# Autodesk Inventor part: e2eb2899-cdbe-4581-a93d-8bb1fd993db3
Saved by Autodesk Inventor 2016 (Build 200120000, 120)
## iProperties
Created: 2017-09
Part Number: e2eb2899-cdbe-4581-a93d-8bb1fd993db3
Material: Generic
Document SubType Name: Modeling
Designer: Administrator
Appearance: Generic
Author: Administrator
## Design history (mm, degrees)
feature "Body1"
body "Solid1"
